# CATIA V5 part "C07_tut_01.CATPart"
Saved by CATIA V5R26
Part number: Part1
Bounding box of the stored display mesh (mm): x -150 to 150, y -150 to 150, z -127.513 to 0
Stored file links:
  D:\_Deepak\CATIA\CATIA V5 2015 Parts Files\Tutorial Files\Tutorials\c07_catia_v5_6r2015_tut\C07_tut_01.CATPart
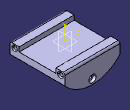
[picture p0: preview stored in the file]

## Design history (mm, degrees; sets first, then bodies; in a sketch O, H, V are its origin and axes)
Body1 (main body)
  Sketch1 on zx-plane, origin (0, 0, 0), H (-1, 0, 0), V (0, 0, 1)
    point P1 (-150, 0)
    line L1 (-150, 0) -> (150, 0)
    point P2 (150, 0)
    line L2 (150, 0) -> (150, -60)
    point P3 (150, -60)
    point P4 (-150, -60)
    point P5 (-150, 0)
    line L3 (-150, 0) -> (-150, -60)
    arc A1 centre (0, 72.2876) radius 200 from (150, -60) to (-150, -60) cw
    point P7 (0, -127.7124)
    length L1 = 300
    length L2 = 60
    radius A1 = 200
    horizontal: L1 H
    vertical: L2 V
    symmetry: P1 P2 V, P3 P4 V, P2 P5 V, L2 L3 V
    coincidence: L1 H, A1 P7, P7 V, P1 P5
  Pad1: profile Sketch1, direction (0, 1, 0), length 150, mirrored extent
  Sketch2 on yz-plane, origin (0, 0, 0), H (0, 1, 0), V (0, 0, 1)
    line L1 (100, 0) -> (-100, 0)
    reference projected line E1 (-150, 0) -> (150, 0) from edge [face of Pad1 from Sketch1.L3 | face of Pad1 from Sketch1.L1]
    line L2 (-100, 0) -> (-100, -25)
    line L3 (-100, -25) -> (100, -25)
    line L4 (100, -25) -> (100, 0)
    length L1 = 200
    length L4 = 25
    horizontal: L1 H, L3 H
    coincidence: L1 E1
    vertical: L2 V, L4 V
  Pocket1: profile Sketch2, direction (-1, 0, 0), length 150, mirrored extent
  Fillet1: radius 10, on edge [start face of Pad1 | face of Pad1 from Sketch1.L1]; edge [face of Pad1 from Sketch1.L1 | end face of Pad1]
  Sketch3 on yz-plane, origin (0, 0, 0), H (0, 1, 0), V (0, 0, 1)
    point P1 (-125, -20)
    point P2 (125, -20)
    reference projected line E1 (150, 0) -> (150, -60) from edge [face of Pad1 from Sketch1.L3 | end face of Pad1]
    reference projected line E2 (-150, 0) -> (150, 0) from edge [face of Pad1 from Sketch1.L3 | face of Pad1 from Sketch1.L1]
    distance P2 E1 = 25
    distance P2 E2 = 20
    symmetry: P1 P2 V
  Sketch4 on face of Pad1 from Sketch1.L3, origin (150, 125, -20), H (0, 1, 0), V (0, 0, 1)
    point P1 (0, 0)
    reference projected point E1 (0, 0) from Sketch3.P2
    coincidence: E1 P1
  Hole1: placed by Sketch4, at (150, 125, -20) direction (-1, 0, 0), diameter 20, through (limit type 3), countersink depth 5, countersink angle 90
  Sketch5 on face of Pad1 from Sketch1.L3, origin (150, -125, -20), H (0, 1, 0), V (0, 0, 1)
    point P1 (0, 0)
    reference projected point E1 (0, 0) from Sketch3.P1
    coincidence: E1 P1
  Hole2: placed by Sketch5, at (150, -125, -20) direction (-1, 0, 0), diameter 20, through (limit type 3), countersink depth 5, countersink angle 90
  Sketch6 on zx-plane, origin (0, 0, 0), H (-1, 0, 0), V (0, 0, 1)
    point P1 (0, -100)
    distance P1 H = 100
    coincidence: P1 V
  Sketch7 on end face of Pad1, origin (0, 150, -100), H (1, 0, 0), V (0, 0, -1)
    point P1 (0, 0)
    reference projected point E1 (0, 0) from Sketch6.P1
    coincidence: E1 P1
  Hole3: placed by Sketch7, at (0, 150, -100) direction (0, -1, 0), diameter 20, through (limit type 3), counterbore diameter 40, counterbore depth 15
